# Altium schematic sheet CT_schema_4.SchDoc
size 266 x 267 mm
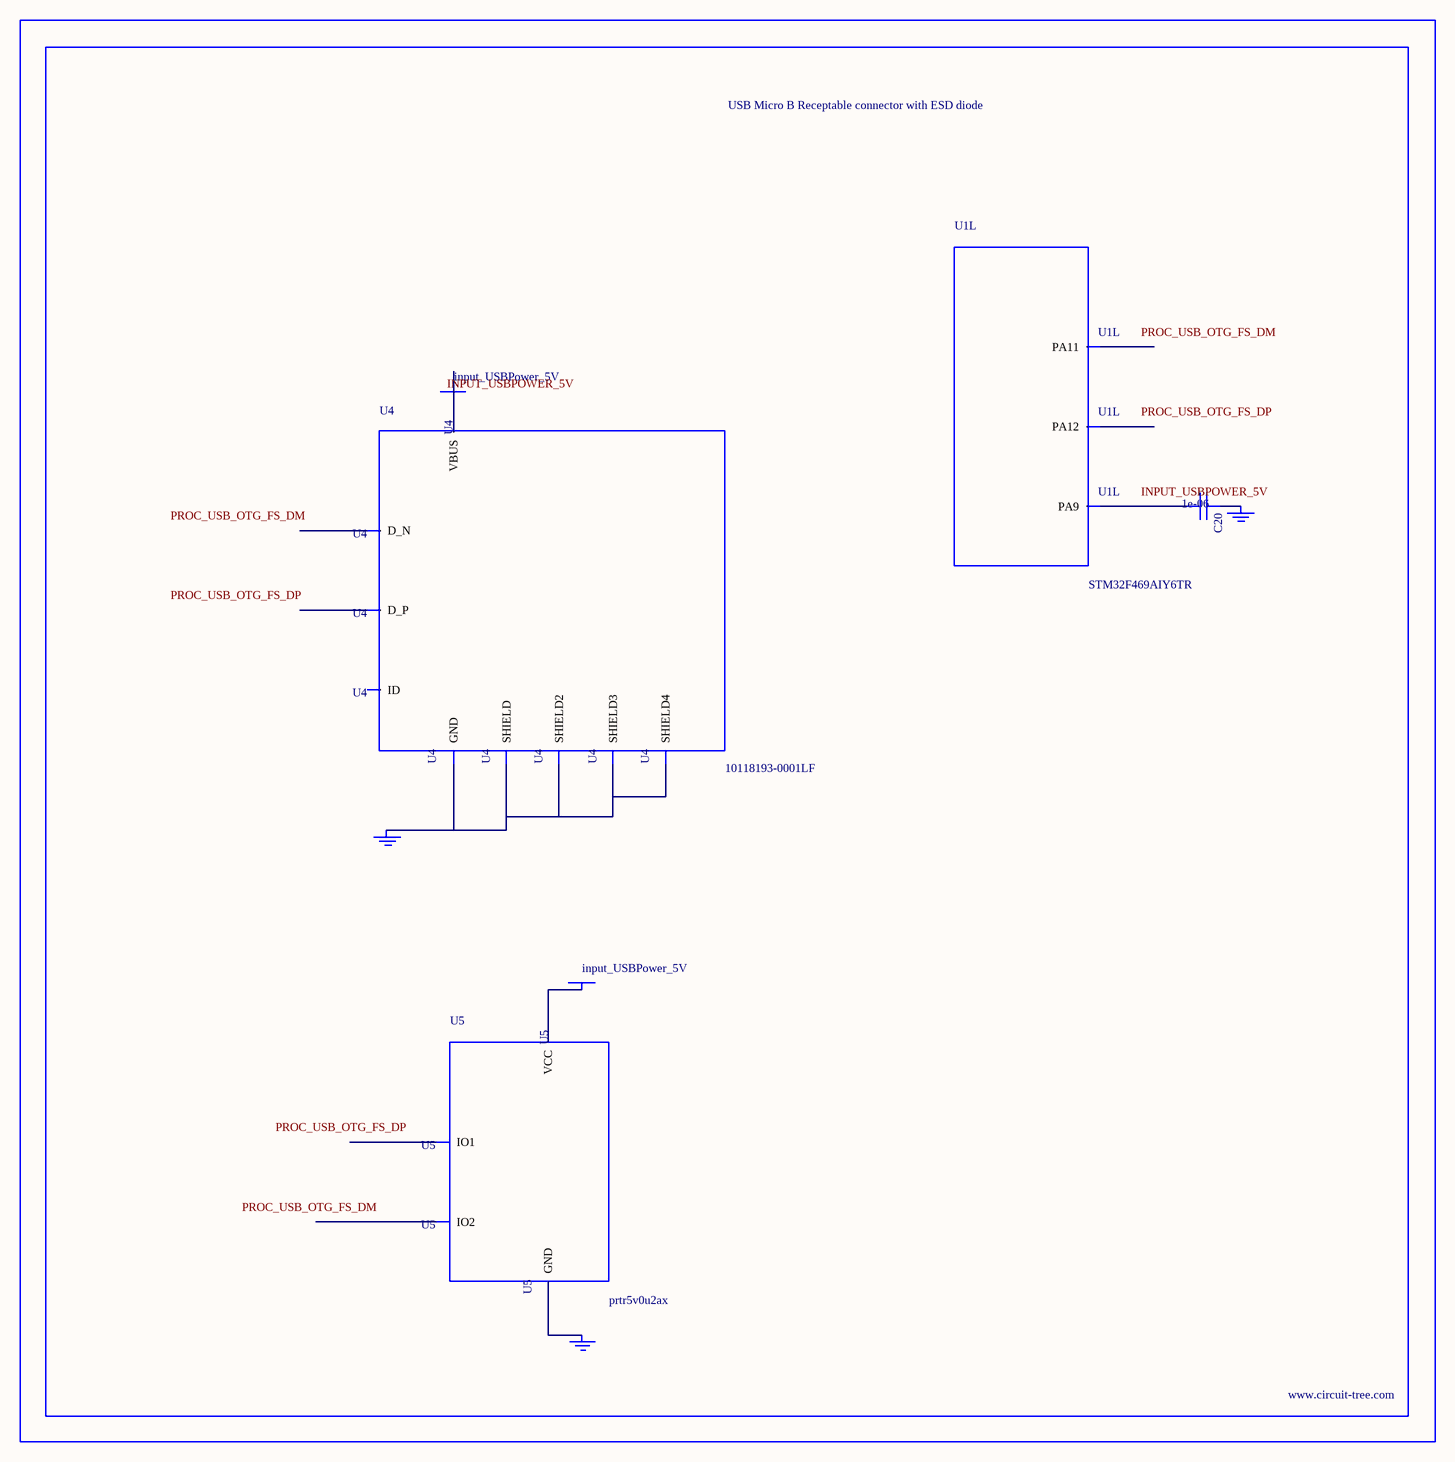
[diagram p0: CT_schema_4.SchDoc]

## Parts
BORDER3  (no value)
C20  1e-06  [C0603]
GND_INSTANCE_3_0  (no value)
GND_INSTANCE_3_1  (no value)
GND_INSTANCE_3_2  (no value)
POWER_INSTANCE_3_0  input_USBPower_5V
POWER_INSTANCE_3_1  input_USBPower_5V
U1  STM32F469AIY6TR  [WLCSP168]  (part L of 14)
U4  10118193-0001LF  [FCI_10118193-0001LF]
U5  prtr5v0u2ax  [SOT143B]

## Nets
NetC20_1: C20.1 GND_INSTANCE_3_1.0(GND)
NetC20_2: C20.2 U1.E2(PA9)
NetGND_INSTANCE_3_0_0: GND_INSTANCE_3_0.0(GND) U4.5(GND) U4.6(SHIELD) U4.7(SHIELD2) U4.8(SHIELD3) U4.9(SHIELD4)
NetGND_INSTANCE_3_2_0: GND_INSTANCE_3_2.0(GND) U5.1(GND)
NetPOWER_INSTANCE_3_0_0: POWER_INSTANCE_3_0.0(PWR) U4.1(VBUS)
NetPOWER_INSTANCE_3_1_0: POWER_INSTANCE_3_1.0(PWR) U5.4(VCC)

Not connected (* = marked no-connect by the designer): U1 F6(PA12) F7(PA11); U4 2(D_N) 3(D_P) 4(ID); U5 2(IO1) 3(IO2)

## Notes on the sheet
- Labels drawn without touching a wire or pin: INPUT_USBPOWER_5V, PROC_USB_OTG_FS_DM, PROC_USB_OTG_FS_DP

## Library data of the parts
BORDER3 = BORDER_PAGE3
C20 = C0603C105K3RACTU
GND_INSTANCE_3_0-GND_INSTANCE_3_2 = GND
POWER_INSTANCE_3_0 POWER_INSTANCE_3_1 = PWR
